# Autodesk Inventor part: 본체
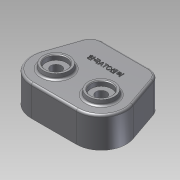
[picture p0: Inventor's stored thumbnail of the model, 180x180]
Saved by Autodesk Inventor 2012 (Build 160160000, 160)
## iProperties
Created: 2014-12
Part Number: 본체
Material: Default
Document SubType Name: Modeling
Designer: Administrator
Density: 1 g/cm^3
Author: Administrator
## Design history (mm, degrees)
sketch "스케치1"
  geometry: L1 (0, 36)-(-34.162, 36); L2 (0, 36)-(34.162, 36); L3 (-51.181, 23.862)-(-66.565, -20.803); L4 (51.181, 23.862)-(66.565, -20.803); L5 (32.527, -68.527)-(-32.527, -68.527); A1 r 36 centre (-32.527, -32.527) between (-66.565, -20.803) and (-32.527, -68.527); A2 r 36 centre (32.527, -32.527) between (32.527, -68.527) and (66.565, -20.803); A3 r 18 centre (-34.162, 18) between (-34.162, 36) and (-51.181, 23.862); A4 r 18 centre (34.162, 18) between (51.181, 23.862) and (34.162, 36); 3 further points
  constraints: 10 end point, 8 point on circle, 7 tangent, 4 centre point, 4 point on line, 1 collinear, 1 equal radius, 1 parallel
extrude "돌출1" new body sketch "스케치1" distance "d9" = 44; taper "d10" = 0 deg
sketch "스케치2"
  geometry: L1 (34.162, 31)-(-34.162, 31); L2 (-46.453, 22.233)-(-61.837, -22.432); L3 (-32.527, -63.527)-(32.527, -63.527); L4 (61.837, -22.432)-(46.453, 22.233); A1 r 13 centre (-34.162, 18) between (-34.162, 31) and (-46.453, 22.233); A2 r 31 centre (-32.527, -32.527) between (-61.837, -22.432) and (-32.527, -63.527); A3 r 31 centre (32.527, -32.527) between (32.527, -63.527) and (61.837, -22.432); A4 r 13 centre (34.162, 18) between (46.453, 22.233) and (34.162, 31); 6 further points
  constraints: 8 end point, 8 point on circle, 4 centre point
extrude "돌출2" cut sketch "스케치2" distance "d12" = 34; taper "d13" = 0 deg
sketch "스케치3"
  geometry: C1 r 24 at (0, 0); 1 further point
  constraints: 1 centre point, 1 coincident
  dimensions: "d14" = 48 diameter of C1
extrude "돌출3" join sketch "스케치3" distance "d15" = 11; taper "d16" = 0 deg
sketch "스케치4"
  geometry: C1 r 24 at (0, 0) reference; C2 r 20 at (0, 0)
  constraints: 1 centre point, 1 coincident
  dimensions: "d17" = 40 diameter of C2
extrude "돌출4" cut sketch "스케치4" distance "d18" = 12; taper "d19" = 0 deg
sketch "스케치5"
  geometry: C1 r 20 at (0, 0) reference; C2 r 10 at (0, 0)
  constraints: 1 centre point, 1 coincident
  dimensions: "d20" = 20 diameter of C2
extrude "돌출5" cut sketch "스케치5" distance "d21" = 3; taper "d22" = 0 deg
sketch "스케치6"
  geometry: C1 r 24 at (-32.527, -32.527); A1 r 31 centre (-32.527, -32.527) between (-61.837, -22.432) and (-32.527, -63.527) reference
  constraints: 1 centre point, 1 coincident
  dimensions: "d23" = 48 diameter of C1
extrude "돌출6" join sketch "스케치6" distance "d24" = 11; taper "d25" = 0 deg
sketch "스케치7"
  geometry: C1 r 17.5 at (-32.527, -32.527); A1 r 24 centre (-32.527, -32.527) between (-21.111, -11.416) and (-11.416, -21.111) reference
  constraints: 1 centre point, 1 coincident
  dimensions: "d26" = 35 diameter of C1
extrude "돌출7" cut sketch "스케치7" distance "d27" = 11; taper "d28" = 0 deg
sketch "스케치8"
  geometry: C1 r 24 at (32.527, -32.527); A1 r 31 centre (32.527, -32.527) between (32.527, -63.527) and (61.837, -22.432) reference
  constraints: 1 centre point, 1 coincident
  dimensions: "d29" = 48 diameter of C1
extrude "돌출8" join sketch "스케치8" distance "d30" = 11; taper "d31" = 0 deg
sketch "스케치9"
  geometry: C1 r 17.5 at (32.527, -32.527); A1 r 24 centre (32.527, -32.527) between (11.416, -21.111) and (21.111, -11.416) reference
  constraints: 1 centre point, 1 coincident
  dimensions: "d32" = 35 diameter of C1
extrude "돌출9" cut sketch "스케치9" distance "d33" = 11; taper "d34" = 0 deg
sketch "스케치10"
  geometry: C1 r 20 at (-32.527, -32.527); A1 r 36 centre (-32.527, -32.527) between (-66.565, -20.803) and (-32.527, -68.527) reference; 1 further point
  constraints: 1 centre point, 1 coincident
  dimensions: "d35" = 40 diameter of C1
extrude "돌출10" join sketch "스케치10" distance "d36" = 7; taper "d37" = -10 deg
sketch "스케치11"
  geometry: C1 r 18.766 at (0, 0) reference; C2 r 15 at (0, 0); 1 further point
  constraints: 1 centre point, 1 coincident
  dimensions: "d38" = 30 diameter of C2
extrude "돌출11" cut sketch "스케치11" distance "d39" = 7; taper "d40" = 0 deg
sketch "스케치12"
  geometry: C1 r 15 at (0, 0) reference; C2 r 7.75 at (0, 0); 1 further point
  constraints: 1 centre point, 1 coincident
  dimensions: "d41" = 15.5 diameter of C2
extrude "돌출12" cut sketch "스케치12" distance "d42" = 10; taper "d43" = 0 deg
sketch "스케치13"
  geometry: C1 r 20 at (32.527, -32.527); A1 r 36 centre (32.527, -32.527) between (32.527, -68.527) and (66.565, -20.803) reference; 1 further point
  constraints: 1 centre point, 1 coincident
  dimensions: "d44" = 40 diameter of C1
extrude "돌출13" join sketch "스케치13" distance "d45" = 7; taper "d46" = -10 deg
sketch "스케치14"
  geometry: C1 r 18.766 at (0, 0) reference; C2 r 15 at (0, 0); 1 further point
  constraints: 1 centre point, 1 coincident
  dimensions: "d47" = 30 diameter of C2
extrude "돌출14" cut sketch "스케치14" distance "d48" = 7; taper "d49" = 0 deg
sketch "스케치15"
  geometry: C1 r 15 at (0, 0) reference; C2 r 7.75 at (0, 0); 1 further point
  constraints: 1 centre point, 1 coincident
  dimensions: "d50" = 15.5 diameter of C2
extrude "돌출15" cut sketch "스케치15" distance "d51" = 15.5; taper "d52" = 0 deg
sketch "스케치16"
  geometry: L1 (-32.527, -63.527)-(32.527, -63.527) reference; A1 r 8 centre (0, -63.527) between (8, -63.527) and (-8, -63.527)
  constraints: 2 point on circle, 2 point on line, 1 centre point, 1 midpoint
  dimensions: "d53" = 16 diameter of A1
extrude "돌출16" join sketch "스케치16" distance "d54" = 34; taper "d55" = 0 deg
sketch "스케치17"
  geometry: L1 (61.837, -22.432)-(46.453, 22.233) reference; L2 (-46.453, 22.233)-(-61.837, -22.432) reference; A1 r 8 centre (51.7, 7) between (49.095, 14.564) and (54.305, -0.564); A2 r 8 centre (-51.7, 7) between (-54.305, -0.564) and (-49.095, 14.564)
  constraints: 6 point on line, 4 point on circle, 2 centre point
  dimensions: "d58" = 16 diameter of A1; "d59" = 16 diameter of A2
extrude "돌출17" join sketch "스케치17" distance "d60" = 34; taper "d61" = 0 deg
sketch "스케치18"
  geometry: A1 r 8 centre (51.7, 7) between (49.095, 14.564) and (54.305, -0.564) reference; A2 r 8 centre (0, -63.527) between (8, -63.527) and (-8, -63.527) reference; A3 r 8 centre (-51.7, 7) between (-54.305, -0.564) and (-49.095, 14.564) reference; 4 further points
  constraints: 3 coincident
hole "구멍1" sketch "스케치18" at (-51.7, 7), (0, -63.527), (51.7, 7) diameter "d62" = 4.134; stored, may be unused: countersink angle "d66" = 90 deg, drill point angle "d68" = 118 deg; dims "d63" = 20, "d64" = 4, "d65" = 2, "d67" = 23
fillet "모깎기1" dims "d69" = 0.3
fillet "모깎기2" dims "d70" = 0.1
fillet "모깎기3" dims "d71" = 0.3
fillet "모깎기4" dims "d72" = 3
fillet "모깎기5" dims "d73" = 3
fillet "모깎기6" dims "d74" = 3
fillet "모깎기7" dims "d75" = 3
fillet "모깎기8" dims "d76" = 3
chamfer "모따기1" distance "d77" = 1; stored, may be unused: second distance "d78" = 2, angle "d79" = 45 deg
sketch "스케치19"
  geometry: L1 (-24.881, 9.605)-(24.894, 9.605); L2 (24.894, 9.605)-(24.894, 2.4); L3 (24.894, 2.4)-(-24.881, 2.4); L4 (-24.881, 2.4)-(-24.881, 9.605); 1 further point
  constraints: 2 other
feature "엠보싱1" sketch "스케치19" dims "d83" = 1, "d84" = 0
fillet "모깎기9" dims "d85" = 3
node "솔리드1"
